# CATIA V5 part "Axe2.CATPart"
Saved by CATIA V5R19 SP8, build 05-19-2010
Part number: Axe2
Publications: "L", "r"
Bounding box of the stored display mesh (mm): x -15 to 15, y -5 to 5, z -5 to 5
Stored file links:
  C:\Users\ThinkMotion\Desktop\EU_thinkMotion\iao\IAO_MMS_Groupe3\evulliez\evulliez\evulliez\Mecanisme\Axe2.CATPart
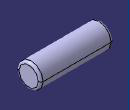
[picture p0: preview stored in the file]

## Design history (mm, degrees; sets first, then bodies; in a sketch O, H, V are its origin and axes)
Parameters
  L = 30 mm
  r = 5 mm
Body1 (main body)
  Point1: (0, 0, 0)
  Line1: type PtDir, RefPoint Point1, Direction (1, 0, 0), Start -15, End 15 {= L /2}
  Sketch1 on yz-plane, origin (0, 0, 0), H (0, 1, 0), V (0, 0, 1)
    circle A1 centre (0, 0) radius 5
    point P1 (0, 0)
    reference projected point E1 (0, 0) from Point1
    radius A1 = 5 {= r}
    coincidence: E1 P1
  Pad1: profile Sketch1, direction (1, 0, 0), length 15 {= L /2}, mirrored extent
  Fillet1: radius 1, on edge [face of Pad1 from Sketch1.A1 | end face of Pad1]; edge [start face of Pad1 | face of Pad1 from Sketch1.A1]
